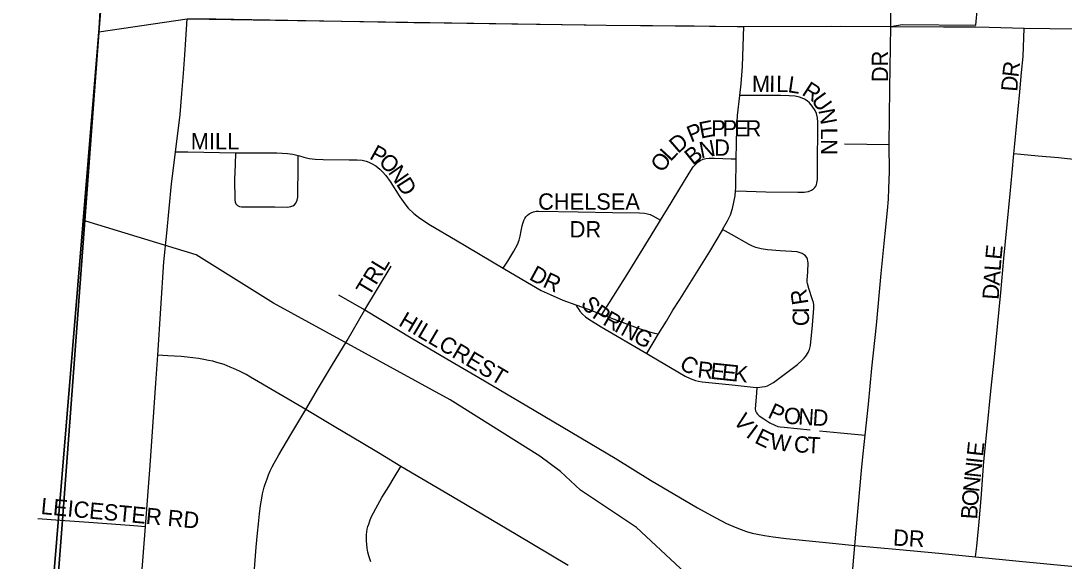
# Model space of a CAD drawing. Extents: x 1410790 to 1770854, y 448063 to 770588.
# Drawn here: x 1514593 to 1517791, y 598966 to 600623 of the extents above; entities that cross this region are included whole.
import ezdxf

# ---------------------------------------------------------------- set-up
doc = ezdxf.new("R2010")
doc.units = 0
for name, color, linetype in [('GM_X_Adjacent_County', 7, 'Continuous'), ('GM_X_City_Street', 7, 'Continuous'), ('GM_X_City_Street_Text', 7, 'Continuous'), ('GM_X_Corporation', 7, 'Continuous'), ('GM_X_County', 7, 'Continuous'), ('GM_X_Minor_River', 7, 'Continuous'), ('GM_X_State_Route', 7, 'Continuous'), ('GM_X_Township', 7, 'Continuous'), ('GM_X_Township_Subdivision', 7, 'Continuous')]:
    doc.layers.add(name, color=color, linetype=linetype)

msp = doc.modelspace()

# ---------------------------------------------------------------- linework, layer by layer
at = {"layer": 'GM_X_Adjacent_County'}
msp.add_lwpolyline([(1515138.6, 605013.3), (1515011.7, 603538), (1514899.6, 602242.1), (1514881.7, 601802.6), (1514877.8, 601372.2), (1514833.2, 600600.5), (1514720.1, 599091.6), (1514692.4, 598721.1), (1514562.7, 596991), (1514515.8, 596366.2), (1515042.7, 596304.1), (1515079.2, 595944.4), (1515011.4, 595290.1), (1514942.3, 594632.2), (1514556.5, 590959.2), (1514551.8, 590905.6), (1514077.4, 585460), (1513734.6, 581107.4), (1513727.5, 580973.9), (1513514.2, 578839.9), (1510501.5, 579143.6)], dxfattribs=at)
at = {"layer": 'GM_X_City_Street'}
for points in [[(1515067.2, 600221.6), (1515070.2, 600244.8), (1515081, 600335.9), (1515086.2, 600400.1), (1515091.4, 600460.9), (1515095.8, 600518.2), (1515098.4, 600566), (1515102.3, 600629.3)], [(1516796.9, 600393.6), (1516801, 600429.9), (1516804.9, 600482.4), (1516807.2, 600544.9), (1516809.4, 600605.6)], [(1517255.5, 600243.9), (1517257.5, 600415.7), (1517260, 600605.6)], [(1517637.3, 600214.6), (1517640.3, 600246), (1517655.5, 600405.2), (1517661.2, 600464.6), (1517665.5, 600513.2), (1517669.4, 600600.6)], [(1516783.9, 600101.5), (1516818, 600100.4), (1516876.9, 600098.7), (1516975.1, 600097.1), (1516994.8, 600097.6), (1517001, 600098.3), (1517007.7, 600100), (1517016.7, 600103.6), (1517023, 600107.5), (1517027.5, 600111.8), (1517030.4, 600116), (1517032.1, 600120.3), (1517033.7, 600126.3), (1517035.2, 600136), (1517035, 600168.8), (1517036, 600312.6), (1517035, 600325.8), (1517031.9, 600338.5), (1517027.9, 600347.4), (1517019.1, 600361.2), (1517010.8, 600371.3), (1517003.5, 600377.9), (1516995.2, 600383), (1516988.3, 600386.2), (1516980, 600389), (1516967.1, 600391.6), (1516948.3, 600393.2), (1516921.4, 600394.1), (1516891.9, 600393.7), (1516826.5, 600393.6), (1516796.9, 600393.6)], [(1516786.3, 600199.7), (1516787.9, 600293.4), (1516790, 600332.4), (1516796.9, 600393.6)], [(1517118.3, 600245.8), (1517255.5, 600243.9)], [(1517181.4, 599352.9), (1517191.5, 599447.5), (1517202.1, 599557.5), (1517215.9, 599690), (1517230.7, 599848.4), (1517243, 599970.9), (1517249.8, 600041.5), (1517252.5, 600076), (1517254.3, 600108.6), (1517255.7, 600161), (1517255.5, 600243.9)], [(1515012.4, 599597.8), (1515031.1, 599884.1), (1515040.2, 599972.1), (1515055, 600122.8), (1515062.8, 600187.5), (1515067.2, 600221.6)], [(1515067.2, 600221.6), (1515105.1, 600220.9), (1515250.7, 600218.5)], [(1515250.7, 600218.5), (1515249.5, 600182), (1515248, 600136.1), (1515248.5, 600073.7), (1515249.5, 600067.3), (1515252.5, 600061.5), (1515257.2, 600056.9), (1515263, 600053.9), (1515269.4, 600052.4), (1515298.9, 600052.6), (1515371.2, 600052.7), (1515410.6, 600051.9), (1515420.3, 600053.2), (1515426.6, 600055.2), (1515432.1, 600058.6), (1515436.3, 600063.7), (1515440.1, 600072.7), (1515441.7, 600082.4), (1515443.1, 600180.9), (1515443.6, 600210.2)], [(1515250.7, 600218.5), (1515260.1, 600218.4), (1515378.2, 600217.6), (1515394.4, 600216.8), (1515410.7, 600216), (1515427, 600214.1), (1515443.6, 600210.2)], [(1515443.6, 600210.2), (1515447.2, 600209.4), (1515460.9, 600205.1), (1515477.2, 600201.2), (1515495.7, 600198.6), (1515520.1, 600197.3), (1515599.7, 600197.1), (1515624.3, 600196.6), (1515639.7, 600195.5), (1515651.2, 600192.9), (1515659.9, 600190), (1515668.3, 600185.9), (1515681.5, 600178.3), (1515693.5, 600168.4), (1515702.1, 600160.1), (1515711.4, 600148.5), (1515725.1, 600130.6), (1515754.8, 600083.6), (1515769.8, 600061.6), (1515780.7, 600048.8), (1515797.4, 600032.3), (1515815.8, 600017.9), (1515849.2, 599996.4), (1515925.4, 599951.3), (1516072.1, 599864.3)], [(1517520.1, 598979.6), (1517523.5, 599011.9), (1517531.2, 599086.7), (1517537.6, 599158.2), (1517545.8, 599272.3), (1517555.8, 599373.3), (1517567, 599487.4), (1517577.6, 599591.5), (1517597.3, 599790.2), (1517606.9, 599894.2), (1517616.8, 599998.2), (1517625.6, 600092.7), (1517631.8, 600157.9), (1517637.3, 600214.6)], [(1518001, 600156.3), (1517996.9, 600160.2), (1517993, 600163.5), (1517989.3, 600166.1), (1517985.6, 600168.2), (1517978.4, 600171.5), (1517971.3, 600174.2), (1517962.6, 600176.8), (1517953.9, 600178.9), (1517937.2, 600182.4), (1517914, 600186), (1517839.3, 600195.2), (1517773.8, 600202.5), (1517711.7, 600208.1), (1517658.8, 600212.8), (1517637.3, 600214.6)], [(1516554.2, 600011.7), (1516575.4, 600046.2), (1516641.8, 600155.6), (1516654.4, 600174.9), (1516660.8, 600182.2), (1516668, 600189.3), (1516675.4, 600194.6), (1516684.3, 600198.8), (1516692.8, 600200.9), (1516703.7, 600202), (1516719.3, 600202), (1516770.2, 600200.2), (1516786.3, 600199.7)], [(1516783.9, 600101.5), (1516784.8, 600109.7), (1516786.3, 600199.7)], [(1516744.5, 599982.6), (1516759.9, 600009.8), (1516768.1, 600028.3), (1516774.6, 600047.9), (1516779.2, 600066.8), (1516782.4, 600086.4), (1516783.9, 600101.5)], [(1516072.1, 599864.3), (1516085.7, 599886.4), (1516104.7, 599917.1), (1516115.2, 599937.5), (1516120.2, 599950.1), (1516123.8, 599962.4), (1516127.2, 599978.5), (1516129.9, 599994.7), (1516132.5, 600004.6), (1516135.2, 600011), (1516138.1, 600016.6), (1516141.6, 600022.1), (1516145.9, 600026.6), (1516151.3, 600030.9), (1516157.2, 600034.3), (1516164.4, 600037.2), (1516172.3, 600038.8), (1516180, 600039.5), (1516301.8, 600037.5), (1516406.9, 600034.8), (1516489.1, 600034.4), (1516505.3, 600033), (1516514, 600031.6), (1516522.1, 600028.8), (1516530, 600024.6), (1516554.2, 600011.7)], [(1516374.1, 599722.6), (1516397.3, 599759.3), (1516451.8, 599845.2), (1516517, 599951.3), (1516547.9, 600001.6), (1516554.2, 600011.7)], [(1516547.4, 599663.1), (1516572.3, 599702.4), (1516592.1, 599735.5), (1516612.9, 599768.6), (1516704.9, 599916.1), (1516743.6, 599981), (1516744.5, 599982.6)], [(1516849.4, 599499), (1516858.1, 599499.3), (1516866, 599500.4), (1516874.4, 599501.9), (1516881.9, 599504.1), (1516889.6, 599507.4), (1516900.7, 599514.3), (1516974.1, 599569.6), (1516988.8, 599582.7), (1516994.7, 599589), (1516999.6, 599595), (1517006.6, 599606), (1517009, 599610.7), (1517010.5, 599615), (1517013.5, 599627.7), (1517020.2, 599689.7), (1517024.6, 599741.9), (1517024.6, 599747), (1517023.9, 599751.7), (1517022.8, 599759), (1517020.4, 599767.7), (1517008.5, 599801.7), (1517004.2, 599817.5), (1517003.4, 599822.1), (1517003.3, 599827.3), (1517005.3, 599853.4), (1517006.3, 599880.4), (1517006.1, 599886), (1517004.7, 599892.4), (1517002.3, 599897.1), (1516998.6, 599902.2), (1516994.1, 599905.9), (1516988.6, 599909.1), (1516982.5, 599911.7), (1516972.7, 599914.1), (1516921.1, 599917.9), (1516881.9, 599920.5), (1516862.4, 599923.4), (1516846.6, 599927.8), (1516836.2, 599931.7), (1516825.6, 599936.8), (1516771.3, 599967.4), (1516744.5, 599982.6)], [(1515647.4, 599736.4), (1515728.2, 599871)], [(1516072.1, 599864.3), (1516128.6, 599830.9), (1516188.6, 599796.5), (1516215.3, 599783.6), (1516254.8, 599766.9), (1516294, 599752.4)], [(1515566.7, 599782.6), (1515614.3, 599755.3), (1515647.4, 599736.4)], [(1515466.4, 599431), (1515505.7, 599497.6), (1515545.8, 599564.5), (1515593.4, 599642.6), (1515647.4, 599736.4)], [(1515647.4, 599736.4), (1515794.3, 599648.3), (1515911, 599579.5), (1515996.8, 599528.9), (1516144.4, 599442.5), (1516414.7, 599282.4), (1516523.5, 599214.9), (1516667.5, 599129.9), (1516721.9, 599100), (1516756.7, 599082), (1516783.2, 599070.2), (1516800.9, 599063), (1516817.4, 599057.4), (1516834.7, 599052.6), (1516851.7, 599048.7), (1516872.5, 599044.8), (1516899.9, 599040.5), (1516939.3, 599035.8), (1516978.8, 599031.8), (1517080.9, 599021.5), (1517130.7, 599016.6), (1517150, 599014.7)], [(1516294, 599752.4), (1516331.8, 599738.4), (1516374.1, 599722.6)], [(1516294, 599752.4), (1516298.2, 599745.4), (1516301.1, 599740.7), (1516306.7, 599733.2), (1516314.9, 599723.7), (1516324.2, 599715.7), (1516334, 599708), (1516371.8, 599684.5), (1516511.6, 599603.2)], [(1516374.1, 599722.6), (1516482.2, 599681.9), (1516520.2, 599669), (1516535.4, 599665), (1516547.4, 599663.1)], [(1516511.6, 599603.2), (1516547.4, 599663.1)], [(1516511.6, 599603.2), (1516522, 599597.2), (1516629.4, 599533.9), (1516644.6, 599526.1), (1516653.1, 599522.9), (1516661.3, 599520.5), (1516670.9, 599518.2), (1516681.9, 599516.4), (1516773.2, 599507), (1516838.6, 599500.2), (1516849.4, 599499)], [(1514974.8, 599072.9), (1514989.4, 599259.5), (1515006.8, 599512.1), (1515012.4, 599597.8)], [(1515466.4, 599431), (1515297.1, 599530.8), (1515283.3, 599538.7), (1515263.2, 599549.1), (1515245, 599557.3), (1515235, 599561.5), (1515225.4, 599565.2), (1515216.1, 599568.7), (1515205.5, 599572.4), (1515193.6, 599575.6), (1515181.2, 599578.9), (1515168.4, 599581.7), (1515153.4, 599584.5), (1515137.4, 599587.1), (1515120.5, 599589.6), (1515103.3, 599591.5), (1515084.9, 599593.2), (1515043.4, 599596), (1515012.4, 599597.8)], [(1516849.4, 599499), (1516848, 599481.6), (1516844, 599433.5), (1516845.5, 599426.7), (1516848.3, 599420.8), (1516851.5, 599416.6), (1516856.1, 599412), (1516870.4, 599402.1), (1516889.7, 599390), (1516904.4, 599383.1), (1516913.7, 599379.4), (1516921.1, 599378), (1516932.9, 599376.9), (1517013.1, 599369.2)], [(1515285.7, 598596.2), (1515293.5, 598738.1), (1515305.3, 598888.4), (1515314.5, 599009.4), (1515318.2, 599051.9), (1515321.2, 599081), (1515324.7, 599111.8), (1515327.7, 599136.5), (1515329.3, 599148.1), (1515331.3, 599159.1), (1515333.8, 599172.2), (1515336.9, 599184.7), (1515339, 599193.5), (1515341.9, 599202.6), (1515344.5, 599210.6), (1515347.6, 599219.1), (1515351.9, 599230.6), (1515357.6, 599243.4), (1515363.6, 599255.4), (1515369.9, 599266.8), (1515383.7, 599292.6), (1515420.7, 599354.5), (1515466.4, 599431)], [(1515758.2, 599256), (1515688.9, 599298.2), (1515636.3, 599330), (1515558.5, 599376.3), (1515466.4, 599431)], [(1517041.6, 599365.9), (1517106.3, 599360.1), (1517181.4, 599352.9)], [(1517150, 599014.7), (1517164.7, 599187.2), (1517170.8, 599255), (1517175.2, 599295.6), (1517181.4, 599352.9)], [(1515665.8, 598964.3), (1515662.6, 598973.8), (1515659.7, 598983), (1515657.2, 598994.1), (1515655, 599005.6), (1515653.5, 599017.8), (1515652.8, 599028.4), (1515652.3, 599037.5), (1515652.8, 599048), (1515653.5, 599055.9), (1515654.9, 599064.2), (1515656.9, 599072.2), (1515659.4, 599080), (1515662.8, 599089.8), (1515667.4, 599101.4), (1515674, 599114.2), (1515680.9, 599127.5), (1515699.8, 599161.8), (1515720.6, 599195.1), (1515737.7, 599222.8), (1515758.2, 599256)], [(1516271.3, 598952.6), (1516111.7, 599047.8), (1515933.3, 599153.5), (1515758.2, 599256)], [(1514645.4, 599096.9), (1514713.8, 599091.8), (1514815.2, 599084.7), (1514939.4, 599075.8), (1514974.8, 599072.9)], [(1514948.3, 598703.5), (1514954.4, 598798.7), (1514962.6, 598915.6), (1514974.8, 599072.9)], [(1517048.3, 597867.7), (1517062.7, 598028.5), (1517070.8, 598132.8), (1517080.1, 598242.9), (1517091.7, 598374.3), (1517098.2, 598442.4), (1517110.8, 598578), (1517117.4, 598653.8), (1517126.3, 598748.1), (1517133.4, 598819), (1517139.8, 598894.4), (1517150, 599014.7)], [(1517150, 599014.7), (1517286.9, 599002.5), (1517407.2, 598990.7), (1517520.1, 598979.6)], [(1517520.1, 598979.6), (1517653.6, 598966.5), (1517802.6, 598952.4), (1517903.6, 598942.3), (1517969.4, 598936.1)]]:
    msp.add_lwpolyline(points, dxfattribs=at)
at = {"layer": 'GM_X_Corporation'}
for points in [[(1515066.2, 604167.4), (1514899.6, 602242.1), (1514881.7, 601802.6), (1514875.4, 601107.6), (1514832.3, 600589.1), (1514541.3, 597088.3), (1514481.9, 596373.1), (1515042.7, 596304.1), (1515101, 596296.9), (1515075.4, 595899.6), (1514942.3, 594632.2), (1514834, 593600.7), (1510778.9, 594171.7)], [(1514541.3, 597088.3), (1514832.3, 600589.1), (1515102.3, 600629.3), (1516387.6, 600609.8), (1516809.4, 600605.6), (1517078.4, 600606.6), (1517260, 600605.6), (1517295.2, 600611.7), (1517520.9, 600609.6), (1517526.3, 600665), (1517282.2, 600659.6), (1517259.7, 600656), (1517261.1, 600887), (1517544.7, 600884.9), (1517586.9, 601390.4), (1517738.1, 601389), (1517757.4, 601605), (1517796.8, 602009.2)]]:
    msp.add_lwpolyline(points, dxfattribs=at)
at = {"layer": 'GM_X_County'}
msp.add_lwpolyline([(1515138.6, 605013.3), (1515011.7, 603538), (1514899.6, 602242.1), (1514881.7, 601802.6), (1514877.8, 601372.2), (1514833.2, 600600.5), (1514720.1, 599091.6), (1514692.4, 598721.1), (1514562.7, 596991), (1514515.8, 596366.2), (1515042.7, 596304.1), (1515079.2, 595944.4), (1515011.4, 595290.1), (1514942.3, 594632.2), (1514556.5, 590959.2), (1514551.8, 590905.6), (1514077.4, 585460)], dxfattribs=at)
at = {"layer": 'GM_X_Minor_River'}
msp.add_lwpolyline([(1517902.7, 598134.1), (1517779.2, 598170.9), (1517586.8, 598165), (1517535.2, 598186.2), (1517168.2, 598477), (1517123.1, 598528.1), (1516881.9, 598695.8), (1516480.5, 599069.5), (1516308.4, 599183.5), (1516247.4, 599241), (1516184.2, 599288.5), (1515909.1, 599460.9), (1515368, 599757.4), (1515130.4, 599905), (1514791.8, 600008.3)], dxfattribs=at)
at = {"layer": 'GM_X_State_Route'}
for points in [[(1515102.3, 600629.3), (1515190.9, 600628.8), (1515797.6, 600617.8)], [(1515797.6, 600617.8), (1515821.3, 600617.4), (1516098.4, 600613.9), (1516326.4, 600610.4), (1516387.6, 600609.8), (1516529.6, 600608.4), (1516657.6, 600607.2), (1516788.7, 600605.5), (1516809.4, 600605.6), (1517106.7, 600606.7), (1517260, 600605.6)], [(1517260, 600605.6), (1517421.2, 600604.4), (1517520.9, 600604.1), (1517561.9, 600603.1)], [(1517561.9, 600603.1), (1517669.4, 600600.6), (1517747.9, 600599.1), (1517910.7, 600597.9)]]:
    msp.add_lwpolyline(points, dxfattribs=at)
at = {"layer": 'GM_X_Township'}
msp.add_lwpolyline([(1514077.4, 585460), (1514551.8, 590905.6), (1514556.5, 590959.2), (1514942.3, 594632.2), (1515011.4, 595290.1), (1515079.2, 595944.4), (1515042.7, 596304.1), (1514515.8, 596366.2), (1514562.7, 596991), (1514692.4, 598721.1), (1514720.1, 599091.6), (1514833.2, 600600.5), (1514877.8, 601372.2), (1514881.7, 601802.6), (1514899.6, 602242.1), (1515011.7, 603538), (1515138.6, 605013.3)], dxfattribs=at)
at = {"layer": 'GM_X_Township_Subdivision'}
msp.add_lwpolyline([(1517260, 600605.6), (1517259.4, 600706.5), (1517260, 600772.9), (1517261.1, 600887)], dxfattribs=at)

# ---------------------------------------------------------------- texts
at = {"layer": 'GM_X_City_Street_Text'}
for s, rotation, p in [('DR', 90, (1517251.9, 600434.8)), ('R', 83.3058, (1517651.1, 600448)), ('M', 359.7814, (1516834.2, 600404.6)), ('I', 359.7779, (1516887, 600404.4)), ('L', 359.7814, (1516909, 600404.3)), ('L', 351.582, (1516942.3, 600404.3)), ('R', 327.1116, (1516984.6, 600397.6)), ('D', 85.5032, (1517647.7, 600404.6)), ('U', 305.7333, (1517014.3, 600379.5)), ('N', 280.7956, (1517037.8, 600349)), ('P', 21.8674, (1516647.1, 600249.2)), ('E', 11.2188, (1516677.4, 600261.6)), ('P', 0, (1516709.3, 600268.2)), ('P', 0, (1516744.5, 600268.2)), ('E', 0, (1516779.7, 600268.2)), ('R', 0, (1516814.9, 600268.2)), ('MILL', 0, (1515113.9, 600228.6)), ('D', 40.8621, (1516607.5, 600214.1)), ('L', 270.1093, (1517046, 600295.1)), ('P', 331.021, (1515658.8, 600201.5)), ('B', 38.8229, (1516653, 600178.5)), ('N', 11.1513, (1516678.1, 600200.6)), ('D', 0.7869, (1516718.9, 600208.9)), ('N', 269.8032, (1517046, 600259.9)), ('O', 316.2442, (1515686.9, 600186.5)), ('O', 54.0088, (1516559.8, 600154.9)), ('L', 47.2026, (1516584.7, 600189.2)), ('N', 305.0422, (1515717, 600158)), ('D', 302.5869, (1515741.9, 600122.4)), ('CHELSEA', 0, (1516178.7, 600043.8)), ('DR', 0, (1516275.5, 599958.8)), ('E', 84.3492, (1517599.2, 599889.2)), ('TRL', 58.6701, (1515660.3, 599775.3)), ('L', 85.7469, (1517596.6, 599854.4)), ('D', 331.3965, (1516148.3, 599831.3)), ('A', 86.0187, (1517593.6, 599810.6)), ('R', 335.2905, (1516190.1, 599808.6)), ('R', 98.7465, (1517007.9, 599756)), ('D', 86.0296, (1517590.5, 599766.7)), ('S', 307.5203, (1516307.2, 599754.9)), ('HILLCREST', 329.4195, (1515748.1, 599690.4)), ('P', 326.0129, (1516341.5, 599714.9)), ('R', 330.1419, (1516374, 599693.2)), ('C', 91.0443, (1517009.7, 599687.1)), ('I', 91.0269, (1517009, 599726.6)), ('I', 331.0833, (1516409.1, 599673)), ('N', 331.2646, (1516428.5, 599662.3)), ('G', 331.25, (1516467.1, 599641.2)), ('C', 325.9799, (1516608.2, 599561.3)), ('R', 353.5541, (1516665.4, 599530.1)), ('E', 353.8859, (1516705.1, 599525.6)), ('E', 353.9816, (1516740.2, 599521.9)), ('K', 353.9827, (1516775.2, 599518.2)), ('P', 335.3107, (1516879.8, 599407.7)), ('V', 306.7737, (1516775.8, 599395.4)), ('O', 356.4631, (1516931.2, 599388.1)), ('N', 356.3037, (1516975.1, 599385.4)), ('D', 356.3037, (1517019, 599382.6)), ('I', 323.3674, (1516813.3, 599349)), ('E', 333.8999, (1516839.5, 599330.6)), ('W', 351.5477, (1516887.1, 599310.2)), ('C', 356.5979, (1516961.9, 599300.5)), ('T', 356.8287, (1517001.7, 599298.2)), ('E', 83.8344, (1517542.5, 599285.6)), ('I', 83.8239, (1517540.2, 599263.8)), ('N', 83.8348, (1517535.5, 599220)), ('N', 83.9023, (1517530.8, 599176.3)), ('O', 85.2509, (1517527.2, 599132.8)), ('LEICESTER RD', 354.6462, (1514652.7, 599111)), ('B', 86.1237, (1517524.5, 599093.4)), ('DR', 356.989, (1517266, 599014.2))]:
    msp.add_text(s, height=50, rotation=rotation, dxfattribs=at).set_placement(p)

doc.saveas('drawing.dxf')
